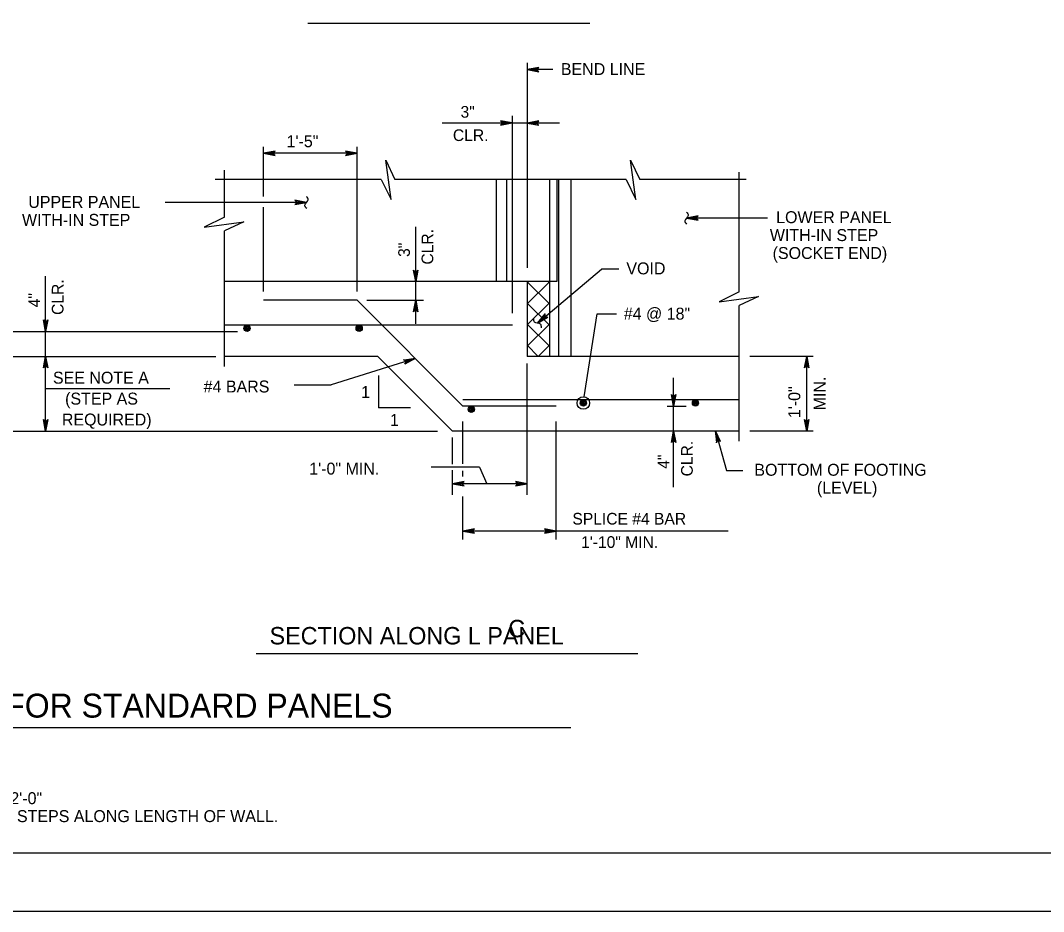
# Model space of a CAD drawing. Extents: x 3385 to 6532, y -616 to 1166.
# Drawn here: x 4880.9 to 5143.7, y -616.3 to -387.3 of the extents above; entities that cross this region are included whole.
import ezdxf

# ---------------------------------------------------------------- set-up
doc = ezdxf.new("R2010")
doc.units = 0
for name, color, linetype in [('1', 7, 'Continuous'), ('2', 7, 'Continuous'), ('PLT-BNDY', 7, 'Continuous')]:
    doc.layers.add(name, color=color, linetype=linetype)

msp = doc.modelspace()

# ---------------------------------------------------------------- linework, layer by layer
at = {"layer": '1'}
for p, q in [((4954.78, -387.98), (5027.18, -387.98)), ((5011.12, -398.17), (5011.12, -450.87)), ((5017.68, -399.93), (5011.12, -399.93)), ((5007.31, -462.54), (5007.31, -411.77)), ((5019.41, -413.68), (4989.22, -413.68)), ((4943.37, -432.54), (4943.37, -419.8)), ((4967.37, -456.91), (4967.37, -419.8)), ((4967.37, -421.44), (4943.37, -421.44)), ((4933.29, -437.85), (4933.29, -425.73)), ((4973.6, -428.13), (4930.89, -428.13)), ((5036.49, -428.13), (4977.12, -428.13)), ((5003.12, -428.13), (5003.12, -454.41)), ((5005.74, -428.13), (5005.74, -454.41)), ((5016.78, -428.13), (5016.78, -454.41)), ((5018.72, -428.13), (5018.72, -454.41)), ((5019.12, -428.13), (5019.12, -473.62)), ((5022.34, -428.13), (5022.34, -473.62)), ((5067.33, -428.13), (5040.01, -428.13)), ((5065.57, -457.05), (5065.57, -426.29)), ((4954.39, -434.07), (4918.07, -434.07)), ((4943.37, -456.91), (4943.37, -435.24)), ((5072.83, -438.09), (5052.03, -438.09)), ((4933.29, -476.24), (4933.29, -441.37)), ((4982.46, -465.26), (4982.46, -440.33)), ((5013.76, -465.08), (5030.22, -451.18)), ((5034.63, -451.18), (5030.22, -451.18)), ((4887.36, -492.82), (4887.36, -453.04)), ((5018.72, -454.41), (4933.29, -454.41)), ((5011.12, -454.41), (5011.12, -473.62)), ((5011.12, -454.69), (5011.39, -454.41)), ((5011.12, -460.12), (5016.78, -454.45)), ((5016.78, -460.15), (5011.12, -454.49)), ((5016.78, -454.72), (5016.47, -454.41)), ((5016.78, -454.41), (5016.78, -473.62)), ((4967.37, -459.22), (4943.37, -459.22)), ((4994.57, -486.42), (4967.37, -459.22)), ((4969.91, -459.22), (4984.49, -459.22)), ((5011.12, -465.55), (5016.78, -459.88)), ((5016.78, -465.58), (5011.12, -459.92)), ((5065.57, -495.44), (5065.57, -460.57)), ((5025.76, -484.04), (5029.1, -462.66)), ((5029.1, -462.66), (5034.03, -462.66)), ((4861.37, -467.22), (4936.63, -467.22)), ((5007.31, -465.62), (4933.29, -465.62)), ((5011.12, -470.98), (5016.78, -465.31)), ((5016.78, -471.01), (5011.12, -465.35)), ((5013.95, -473.62), (5011.12, -470.78)), ((5013.91, -473.62), (5016.78, -470.74)), ((4867.35, -473.62), (4931.14, -473.62)), ((4972.72, -473.62), (4933.29, -473.62)), ((4982.33, -474.18), (4960.74, -480.97)), ((4991.92, -492.82), (4972.72, -473.62)), ((5065.57, -473.62), (5011.12, -473.62)), ((5011.12, -509.21), (5011.12, -475.49)), ((5084.56, -473.62), (5068.31, -473.62)), ((5082.91, -492.82), (5082.91, -473.62)), ((4951.24, -480.97), (4960.74, -480.97)), ((4972.91, -478.58), (4972.91, -486.82)), ((5048.69, -507.2), (5048.69, -479.1)), ((4887.36, -481.87), (4919.29, -481.87)), ((5065.57, -484.82), (4994.57, -484.82)), ((5025.52, -485.62), (5025.52, -485.62)), ((4981.15, -486.82), (4972.91, -486.82)), ((5018.57, -486.42), (4994.57, -486.42)), ((5047.05, -486.42), (5051.95, -486.42)), ((4994.57, -501.27), (4994.57, -490.38)), ((5018.57, -520.71), (5018.57, -490.38)), ((4809.34, -492.82), (4988.09, -492.82)), ((5065.57, -492.82), (4991.92, -492.82)), ((5059.43, -492.82), (5062.33, -502.95)), ((5084.56, -492.82), (5068.31, -492.82)), ((4991.92, -501.29), (4991.92, -494.51)), ((4998.85, -502.14), (4986.41, -502.14)), ((4991.92, -509.21), (4991.92, -502.91)), ((4994.57, -504.52), (4994.57, -503.07)), ((4998.85, -502.14), (5000.75, -506.37)), ((5062.33, -502.95), (5066.52, -502.95)), ((5011.12, -506.37), (4991.92, -506.37)), ((4994.57, -520.71), (4994.57, -509.63)), ((5062.72, -518.51), (4994.57, -518.51)), ((4941.46, -549.95), (5039.53, -549.95)), ((4774.51, -569.05), (5022.29, -569.05))]:
    msp.add_line(p, q, dxfattribs=at)
for points in [[(5011.12, -399.93), (5014.1, -400.49), (5013.87, -400.33), (5013.75, -400.13), (5013.72, -399.93), (5013.75, -399.73), (5013.87, -399.53), (5014.1, -399.37), (5011.12, -399.93), (5013.87, -399.53), (5013.75, -399.73), (5011.12, -399.93), (5013.72, -399.93), (5013.75, -400.13), (5011.12, -399.93), (5013.87, -400.33)], [(5007.19, -413.64), (5004.21, -413.08), (5004.44, -413.24), (5004.56, -413.44), (5004.59, -413.64), (5004.56, -413.84), (5004.44, -414.04), (5004.21, -414.2), (5007.19, -413.64), (5004.44, -414.04), (5004.56, -413.84), (5007.19, -413.64), (5004.59, -413.64), (5004.56, -413.44), (5007.19, -413.64), (5004.44, -413.24)], [(5011.12, -413.68), (5014.1, -414.23), (5013.87, -414.08), (5013.75, -413.88), (5013.72, -413.68), (5013.75, -413.48), (5013.87, -413.28), (5014.1, -413.12), (5011.12, -413.68), (5013.87, -413.28), (5013.75, -413.48), (5011.12, -413.68), (5013.72, -413.68), (5013.75, -413.88), (5011.12, -413.68), (5013.87, -414.08)], [(4943.37, -421.44), (4946.35, -422), (4946.12, -421.84), (4946, -421.64), (4945.97, -421.44), (4946, -421.24), (4946.12, -421.04), (4946.35, -420.88), (4943.37, -421.44), (4946.12, -421.04), (4946, -421.24), (4943.37, -421.44), (4945.97, -421.44), (4946, -421.64), (4943.37, -421.44), (4946.12, -421.84)], [(4967.37, -421.44), (4964.38, -420.88), (4964.61, -421.04), (4964.73, -421.24), (4964.77, -421.44), (4964.73, -421.64), (4964.61, -421.84), (4964.38, -422), (4967.37, -421.44), (4964.61, -421.84), (4964.73, -421.64), (4967.37, -421.44), (4964.77, -421.44), (4964.73, -421.24), (4967.37, -421.44), (4964.61, -421.04)], [(4973.6, -428.13), (4976.14, -433.32), (4974.76, -423.17), (4977.12, -428.13)], [(5036.49, -428.13), (5039.03, -433.32), (5037.65, -423.17), (5040.01, -428.13)], [(4954.4, -434.07), (4951.42, -433.51), (4951.65, -433.67), (4951.77, -433.87), (4951.8, -434.07), (4951.77, -434.27), (4951.65, -434.47), (4951.42, -434.63), (4954.4, -434.07), (4951.65, -434.47), (4951.77, -434.27), (4954.4, -434.07), (4951.8, -434.07), (4951.77, -433.87), (4954.4, -434.07), (4951.65, -433.67)], [(4933.29, -437.85), (4928.11, -440.39), (4938.26, -439.01), (4933.29, -441.37)], [(5052.03, -438.09), (5055.02, -438.65), (5054.79, -438.49), (5054.67, -438.29), (5054.63, -438.09), (5054.67, -437.89), (5054.79, -437.69), (5055.02, -437.53), (5052.03, -438.09), (5054.79, -437.69), (5054.67, -437.89), (5052.03, -438.09), (5054.63, -438.09), (5054.67, -438.29), (5052.03, -438.09), (5054.79, -438.49)], [(4982.46, -454.41), (4981.9, -451.43), (4982.06, -451.66), (4982.26, -451.78), (4982.46, -451.81), (4982.66, -451.78), (4982.86, -451.66), (4983.02, -451.43), (4982.46, -454.41), (4982.86, -451.66), (4982.66, -451.78), (4982.46, -454.41), (4982.46, -451.81), (4982.26, -451.78), (4982.46, -454.41), (4982.06, -451.66)], [(5065.57, -457.05), (5060.39, -459.59), (5070.54, -458.21), (5065.57, -460.57)], [(4982.46, -459.22), (4983.02, -462.2), (4982.86, -461.97), (4982.66, -461.85), (4982.46, -461.82), (4982.26, -461.85), (4982.06, -461.97), (4981.9, -462.2), (4982.46, -459.22), (4982.06, -461.97), (4982.26, -461.85), (4982.46, -459.22), (4982.46, -461.82), (4982.66, -461.85), (4982.46, -459.22), (4982.86, -461.97)], [(4887.36, -467.22), (4886.8, -464.23), (4886.96, -464.46), (4887.16, -464.58), (4887.36, -464.62), (4887.56, -464.58), (4887.76, -464.46), (4887.91, -464.23), (4887.36, -467.22), (4887.76, -464.46), (4887.56, -464.58), (4887.36, -467.22), (4887.36, -464.62), (4887.16, -464.58), (4887.36, -467.22), (4886.96, -464.46)], [(5013.76, -465.08), (5015.68, -462.73), (5015.65, -462.87), (5015.61, -463), (5015.63, -463.12), (5015.65, -463.23), (5015.7, -463.32), (5015.75, -463.41), (5015.83, -463.47), (5015.91, -463.54), (5016.02, -463.57), (5016.13, -463.61), (5016.26, -463.6), (5016.4, -463.59), (5013.76, -465.08), (5016.26, -463.6), (5016.13, -463.61), (5013.76, -465.08), (5016.02, -463.57), (5015.91, -463.54), (5013.76, -465.08), (5015.83, -463.47), (5015.75, -463.41), (5013.76, -465.08), (5015.7, -463.32), (5015.65, -463.23), (5013.76, -465.08), (5015.63, -463.12), (5015.61, -463), (5013.76, -465.08), (5015.65, -462.87)], [(4887.36, -473.62), (4887.91, -476.6), (4887.76, -476.37), (4887.56, -476.25), (4887.36, -476.22), (4887.16, -476.25), (4886.96, -476.37), (4886.8, -476.6), (4887.36, -473.62), (4886.96, -476.37), (4887.16, -476.25), (4887.36, -473.62), (4887.36, -476.22), (4887.56, -476.25), (4887.36, -473.62), (4887.76, -476.37)], [(4982.33, -474.18), (4979.65, -475.61), (4979.82, -475.39), (4979.88, -475.16), (4979.85, -474.96), (4979.76, -474.78), (4979.58, -474.62), (4979.32, -474.54), (4982.33, -474.18), (4979.58, -474.62), (4979.76, -474.78), (4982.33, -474.18), (4979.85, -474.96), (4979.88, -475.16), (4982.33, -474.18), (4979.82, -475.39)], [(5082.91, -473.62), (5083.47, -476.6), (5083.31, -476.37), (5083.11, -476.25), (5082.91, -476.22), (5082.71, -476.25), (5082.51, -476.37), (5082.35, -476.6), (5082.91, -473.62), (5082.51, -476.37), (5082.71, -476.25), (5082.91, -473.62), (5082.91, -476.22), (5083.11, -476.25), (5082.91, -473.62), (5083.31, -476.37)], [(5048.69, -486.42), (5048.13, -483.43), (5048.29, -483.66), (5048.49, -483.78), (5048.69, -483.82), (5048.89, -483.78), (5049.09, -483.66), (5049.25, -483.43), (5048.69, -486.42), (5049.09, -483.66), (5048.89, -483.78), (5048.69, -486.42), (5048.69, -483.82), (5048.49, -483.78), (5048.69, -486.42), (5048.29, -483.66)], [(4887.36, -492.82), (4886.8, -489.83), (4886.96, -490.06), (4887.16, -490.18), (4887.36, -490.22), (4887.56, -490.18), (4887.76, -490.06), (4887.91, -489.83), (4887.36, -492.82), (4887.76, -490.06), (4887.56, -490.18), (4887.36, -492.82), (4887.36, -490.22), (4887.16, -490.18), (4887.36, -492.82), (4886.96, -490.06)], [(5082.91, -492.82), (5082.35, -489.83), (5082.51, -490.06), (5082.71, -490.18), (5082.91, -490.22), (5083.11, -490.18), (5083.31, -490.06), (5083.47, -489.83), (5082.91, -492.82), (5083.31, -490.06), (5083.11, -490.18), (5082.91, -492.82), (5082.91, -490.22), (5082.71, -490.18), (5082.91, -492.82), (5082.51, -490.06)], [(5048.69, -492.82), (5049.25, -495.8), (5049.09, -495.57), (5048.89, -495.45), (5048.69, -495.42), (5048.49, -495.45), (5048.29, -495.57), (5048.13, -495.8), (5048.69, -492.82), (5048.29, -495.57), (5048.49, -495.45), (5048.69, -492.82), (5048.69, -495.42), (5048.89, -495.45), (5048.69, -492.82), (5049.09, -495.57)], [(5059.43, -492.82), (5059.71, -495.84), (5059.76, -495.7), (5059.8, -495.57), (5059.88, -495.49), (5059.96, -495.4), (5060.06, -495.36), (5060.15, -495.32), (5060.25, -495.3), (5060.35, -495.29), (5060.46, -495.32), (5060.57, -495.35), (5060.68, -495.44), (5060.79, -495.53), (5059.43, -492.82), (5060.68, -495.44), (5060.57, -495.35), (5059.43, -492.82), (5060.46, -495.32), (5060.35, -495.29), (5059.43, -492.82), (5060.25, -495.3), (5060.15, -495.32), (5059.43, -492.82), (5060.06, -495.36), (5059.96, -495.4), (5059.43, -492.82), (5059.88, -495.49), (5059.8, -495.57), (5059.43, -492.82), (5059.76, -495.7)], [(4991.92, -506.37), (4994.9, -506.93), (4994.67, -506.77), (4994.55, -506.57), (4994.52, -506.37), (4994.55, -506.17), (4994.67, -505.97), (4994.9, -505.81), (4991.92, -506.37), (4994.67, -505.97), (4994.55, -506.17), (4991.92, -506.37), (4994.52, -506.37), (4994.55, -506.57), (4991.92, -506.37), (4994.67, -506.77)], [(5011.12, -506.37), (5008.13, -505.81), (5008.36, -505.97), (5008.48, -506.17), (5008.52, -506.37), (5008.48, -506.57), (5008.36, -506.77), (5008.13, -506.93), (5011.12, -506.37), (5008.36, -506.77), (5008.48, -506.57), (5011.12, -506.37), (5008.52, -506.37), (5008.48, -506.17), (5011.12, -506.37), (5008.36, -505.97)], [(4994.57, -518.51), (4997.55, -519.07), (4997.32, -518.91), (4997.2, -518.71), (4997.17, -518.51), (4997.2, -518.31), (4997.32, -518.11), (4997.55, -517.95), (4994.57, -518.51), (4997.32, -518.11), (4997.2, -518.31), (4994.57, -518.51), (4997.17, -518.51), (4997.2, -518.71), (4994.57, -518.51), (4997.32, -518.91)], [(5018.57, -518.51), (5015.58, -517.95), (5015.81, -518.11), (5015.93, -518.31), (5015.97, -518.51), (5015.93, -518.71), (5015.81, -518.91), (5015.58, -519.07), (5018.57, -518.51), (5015.81, -518.91), (5015.93, -518.71), (5018.57, -518.51), (5015.97, -518.51), (5015.93, -518.31), (5018.57, -518.51), (5015.81, -518.11)]]:
    msp.add_lwpolyline(points, dxfattribs=at)
for centre, radius in [((4939.12, -466.42), 0.8), ((4939.12, -466.42), 0.6), ((4939.12, -466.42), 0.4), ((4939.12, -466.42), 0.2), ((4967.92, -466.42), 0.8), ((4967.92, -466.42), 0.6), ((4967.92, -466.42), 0.4), ((4967.92, -466.42), 0.2), ((5025.52, -485.62), 1.6), ((5025.52, -485.62), 0.8), ((5025.52, -485.62), 0.6), ((5025.52, -485.62), 0.4), ((5025.52, -485.62), 0.2), ((5054.32, -485.62), 0.8), ((5054.32, -485.62), 0.6), ((5054.32, -485.62), 0.4), ((5054.32, -485.62), 0.2), ((4996.72, -487.22), 0.8), ((4996.72, -487.22), 0.6), ((4996.72, -487.22), 0.4), ((4996.72, -487.22), 0.2)]:
    msp.add_circle(centre, radius, dxfattribs=at)
for points in [[(4954.44, -435.63), (4953.97, -434.77), (4954.84, -433.37), (4954.42, -432.52)], [(5052, -436.53), (5052.46, -437.4), (5051.6, -438.79), (5052.01, -439.65)], [(5014.75, -466.3), (5014.54, -465.34), (5012.98, -464.83), (5012.75, -463.91)]]:
    msp.add_spline(points, degree=3, dxfattribs=at)
at = {"layer": '2'}
msp.add_line((5428.34, -601.31), (4642.34, -601.31), dxfattribs=at)
at = {"layer": 'PLT-BNDY'}
msp.add_lwpolyline([(4602.34, -22.31), (5443.34, -22.31), (5443.34, -616.31), (4602.34, -616.31)], close=True, dxfattribs=at)

# ---------------------------------------------------------------- texts
at = {"layer": '1'}
for s, height, p in [('BEND LINE', 3.072, (5019.74, -401.33)), ('3"', 3, (4993.97, -412.28)), ('CLR.', 3, (4992.01, -418.28)), ('1\'-5"', 3.072, (4949.28, -419.87)), ('UPPER PANEL', 3.0721, (4882.92, -435.47)), ('LOWER PANEL', 3.0721, (5075.05, -439.39)), ('WITH-IN STEP', 3.0721, (4881.3, -440.08)), ('WITH-IN STEP', 3.0721, (5073.43, -443.99)), ('(SOCKET END)', 3.0721, (5074.14, -448.6)), ('VOID', 3.072, (5036.57, -452.55)), ('#4 @ 18"', 3.072, (5035.91, -464.18)), ('SEE NOTE A', 3.072, (4889.25, -480.64)), ('#4 BARS', 3.072, (4927.97, -482.91)), ('(STEP AS', 3.072, (4892.38, -486.02)), ('1', 3.07, (4968.43, -484.3)), ('REQUIRED)', 3.072, (4891.55, -491.39)), ('1', 3.07, (4975.85, -491.5)), ('1\'-0" MIN.', 3.072, (4955.1, -504.01)), ('BOTTOM OF FOOTING', 3.0721, (5069.45, -504.31)), ('(LEVEL)', 3.072, (5085.52, -508.91)), ('SPLICE #4 BAR', 3, (5022.71, -516.85)), ('  1\'-10" MIN.', 3, (5022.71, -522.85)), ('C', 4.48, (5006.22, -545.82)), ('SECTION ALONG L PANEL', 4.4801, (4944.91, -547.66)), ('FOOTING STEP DETAILS FOR STANDARD PANELS', 6.144, (4777.02, -566.46)), ('MAXIMUM STEP HEIGHT = 2\'-0"', 3.0721, (4825.24, -588.71)), ('MINIMIZE THE NUMBER OF STEPS ALONG LENGTH OF WALL.', 3.0721, (4825.24, -593.32))]:
    msp.add_text(s, height=height, dxfattribs=at).set_placement(p)
for s, height, p in [('CLR.', 3, (4986.96, -450.03)), ('3"', 3, (4980.96, -448.07)), ('CLR.', 3, (4891.97, -462.97)), ('4"', 3, (4885.97, -461.01)), ('MIN.', 3.072, (5087.76, -487.52)), ('1\'-0"', 3.072, (5081.25, -489.5)), ('CLR.', 3, (5053.63, -504.47)), ('4"', 3, (5047.63, -502.51))]:
    msp.add_text(s, height=height, rotation=90, dxfattribs=at).set_placement(p)

doc.saveas('drawing.dxf')
